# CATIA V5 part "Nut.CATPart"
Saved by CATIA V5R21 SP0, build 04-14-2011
Part number: Nut
Bounding box of the stored display mesh (mm): x -86.603 to 86.603, y -100 to 100, z 0 to 50
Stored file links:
  D:\CATIA V5R21 E-RESOURCES\CATIA-V5R21\catia-v5r21-prt\c16-catia-v5r20-prt\Screw Joint-(Fig16-22)\CAT_V5R21_Nut.CATPart
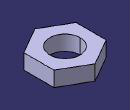
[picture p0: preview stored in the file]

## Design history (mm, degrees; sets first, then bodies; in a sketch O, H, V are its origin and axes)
Body1 (main body)
  Sketch1 on xy-plane, origin (0, 0, 0), H (1, 0, 0), V (0, 1, 0)
    point P1 (86.6025, -50)
    point P2 (86.6025, 50)
    point P3 (0, 100)
    point P4 (-86.6025, 50)
    point P5 (-86.6025, -50)
    point P6 (0, -100)
    point P7 (86.6025, 0)
    line L1 (86.6025, -50) -> (86.6025, 50)
    line L2 (86.6025, 50) -> (0, 100)
    line L3 (0, 100) -> (-86.6025, 50)
    line L4 (-86.6025, 50) -> (-86.6025, -50)
    line L5 (-86.6025, -50) -> (0, -100)
    line L6 (0, -100) -> (86.6025, -50)
    construction line L7 (0, 0) -> (86.6025, 0)
    construction circle A1 centre (0, 0) radius 100
    construction arc A2 centre (-86.6025, -50) radius 100 from (-86.6025, 50) to (0, -100) cw
    construction arc A3 centre (86.6025, 50) radius 100 from (0, 100) to (86.6025, -50) ccw
    circle A4 centre (0, 0) radius 50
    radius A1 = 100
    radius A4 = 50
    horizontal: L7 H
    coincidence: A1 P1, A1 P2, A1 P3, A1 P4, A1 P5, A1 P6, A2 O, A3 O
    midpoint: P7 L1
    parallelism: L1 L4, L2 L5, L3 L6
    vertical: L4 V, L1 V
  Pad1: profile Sketch1, direction (0, 0, 1), length 50
  Thread1: diameter 100, depth 50, pitch 1, on face of Pad1 from Sketch1.A4, from end face of Pad1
